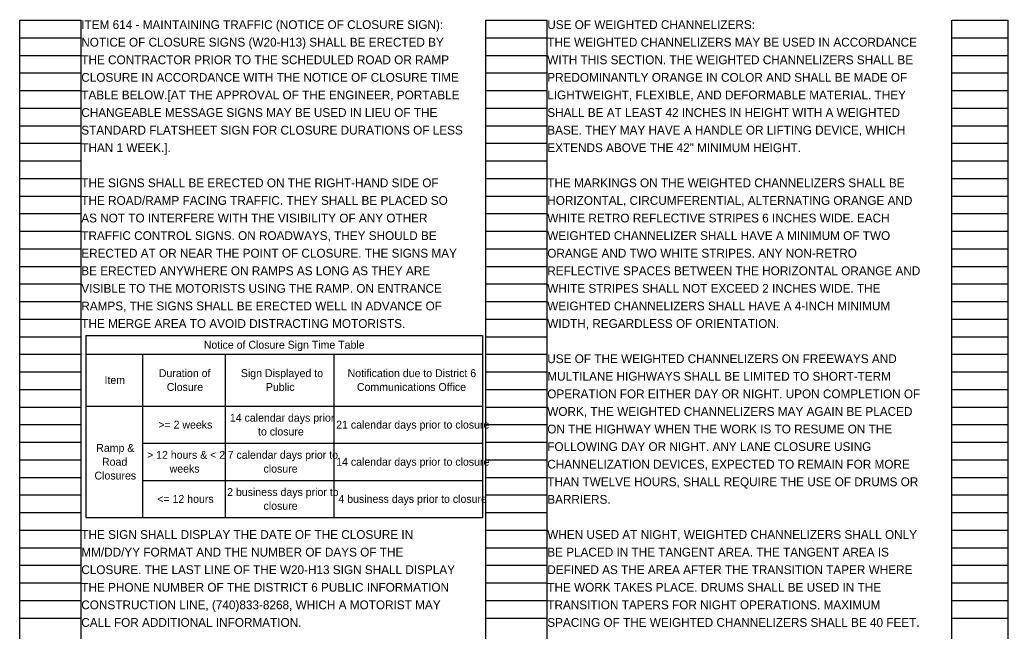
# Model space of a CAD drawing. Extents: x 63 to 145.9, y -75 to 21.1.
# Drawn here: x 79.23 to 94.97, y 11.41 to 21.15 of the extents above; entities that cross this region are included whole.
import ezdxf

# ---------------------------------------------------------------- set-up
doc = ezdxf.new("R2010")
doc.units = 0
doc.layers.add('AP_P_Airside', color=7, linetype='Continuous')
doc.layers.add('SC_Scratch1', color=7, linetype='Continuous')

msp = doc.modelspace()

# ---------------------------------------------------------------- linework, layer by layer
at = {"layer": 'AP_P_Airside'}
for p, q in [((80.277, 16.12), (86.593, 16.12)), ((80.277, 16.12), (80.277, 13.221)), ((86.593, 16.12), (86.593, 13.221)), ((80.277, 15.824), (86.593, 15.824)), ((81.179, 15.824), (81.179, 13.221)), ((82.496, 15.824), (82.496, 13.221)), ((84.226, 15.824), (84.226, 13.221)), ((80.277, 14.996), (86.593, 14.996)), ((81.179, 14.404), (86.593, 14.404)), ((81.179, 13.813), (86.593, 13.813)), ((80.277, 13.221), (86.593, 13.221))]:
    msp.add_line(p, q, dxfattribs=at)
at = {"layer": 'SC_Scratch1'}
for p, q in [((79.226, 0.98), (79.226, 21.14)), ((79.226, 21.14), (80.206, 21.14)), ((80.206, 0.98), (80.206, 21.14)), ((86.646, 0.98), (86.646, 21.14)), ((86.646, 21.14), (87.626, 21.14)), ((87.626, 0.98), (87.626, 21.14)), ((94.066, 0.98), (94.066, 21.14)), ((94.066, 21.14), (94.966, 21.14)), ((94.966, 0.98), (94.966, 21.14)), ((79.226, 20.86), (80.206, 20.86)), ((86.646, 20.86), (87.626, 20.86)), ((94.066, 20.86), (94.966, 20.86)), ((79.226, 20.58), (80.206, 20.58)), ((86.646, 20.58), (87.626, 20.58)), ((94.066, 20.58), (94.966, 20.58)), ((79.226, 20.3), (80.206, 20.3)), ((86.646, 20.3), (87.626, 20.3)), ((94.066, 20.3), (94.966, 20.3)), ((79.226, 20.02), (80.206, 20.02)), ((86.646, 20.02), (87.626, 20.02)), ((94.066, 20.02), (94.966, 20.02)), ((79.226, 19.74), (80.206, 19.74)), ((86.646, 19.74), (87.626, 19.74)), ((94.066, 19.74), (94.966, 19.74)), ((79.226, 19.46), (80.206, 19.46)), ((86.646, 19.46), (87.626, 19.46)), ((94.066, 19.46), (94.966, 19.46)), ((79.226, 19.18), (80.206, 19.18)), ((86.646, 19.18), (87.626, 19.18)), ((94.066, 19.18), (94.966, 19.18)), ((79.226, 18.9), (80.206, 18.9)), ((86.646, 18.9), (87.626, 18.9)), ((94.066, 18.9), (94.966, 18.9)), ((79.226, 18.62), (80.206, 18.62)), ((86.646, 18.62), (87.626, 18.62)), ((94.066, 18.62), (94.966, 18.62)), ((79.226, 18.34), (80.206, 18.34)), ((86.646, 18.34), (87.626, 18.34)), ((94.066, 18.34), (94.966, 18.34)), ((79.226, 18.06), (80.206, 18.06)), ((86.646, 18.06), (87.626, 18.06)), ((94.066, 18.06), (94.966, 18.06)), ((79.226, 17.78), (80.206, 17.78)), ((86.646, 17.78), (87.626, 17.78)), ((94.066, 17.78), (94.966, 17.78)), ((79.226, 17.5), (80.206, 17.5)), ((86.646, 17.5), (87.626, 17.5)), ((94.066, 17.5), (94.966, 17.5)), ((79.226, 17.22), (80.206, 17.22)), ((86.646, 17.22), (87.626, 17.22)), ((94.066, 17.22), (94.966, 17.22)), ((79.226, 16.94), (80.206, 16.94)), ((86.646, 16.94), (87.626, 16.94)), ((94.066, 16.94), (94.966, 16.94)), ((79.226, 16.66), (80.206, 16.66)), ((86.646, 16.66), (87.626, 16.66)), ((94.066, 16.66), (94.966, 16.66)), ((79.226, 16.38), (80.206, 16.38)), ((86.646, 16.38), (87.626, 16.38)), ((94.066, 16.38), (94.966, 16.38)), ((79.226, 16.1), (80.206, 16.1)), ((86.646, 16.1), (87.626, 16.1)), ((94.066, 16.1), (94.966, 16.1)), ((79.226, 15.82), (80.206, 15.82)), ((86.646, 15.82), (87.626, 15.82)), ((94.066, 15.82), (94.966, 15.82)), ((79.226, 15.54), (80.206, 15.54)), ((86.646, 15.54), (87.626, 15.54)), ((94.066, 15.54), (94.966, 15.54)), ((79.226, 15.26), (80.206, 15.26)), ((86.646, 15.26), (87.626, 15.26)), ((94.066, 15.26), (94.966, 15.26)), ((79.226, 14.98), (80.206, 14.98)), ((86.646, 14.98), (87.626, 14.98)), ((94.066, 14.98), (94.966, 14.98)), ((79.226, 14.7), (80.206, 14.7)), ((86.646, 14.7), (87.626, 14.7)), ((94.066, 14.7), (94.966, 14.7)), ((79.226, 14.42), (80.206, 14.42)), ((86.646, 14.42), (87.626, 14.42)), ((94.066, 14.42), (94.966, 14.42)), ((79.226, 14.14), (80.206, 14.14)), ((86.646, 14.14), (87.626, 14.14)), ((94.066, 14.14), (94.966, 14.14)), ((79.226, 13.86), (80.206, 13.86)), ((86.646, 13.86), (87.626, 13.86)), ((94.066, 13.86), (94.966, 13.86)), ((79.226, 13.58), (80.206, 13.58)), ((86.646, 13.58), (87.626, 13.58)), ((94.066, 13.58), (94.966, 13.58)), ((79.226, 13.3), (80.206, 13.3)), ((86.646, 13.3), (87.626, 13.3)), ((94.066, 13.3), (94.966, 13.3)), ((79.226, 13.02), (80.206, 13.02)), ((86.646, 13.02), (87.626, 13.02)), ((94.066, 13.02), (94.966, 13.02)), ((79.226, 12.74), (80.206, 12.74)), ((86.646, 12.74), (87.626, 12.74)), ((94.066, 12.74), (94.966, 12.74)), ((79.226, 12.46), (80.206, 12.46)), ((86.646, 12.46), (87.626, 12.46)), ((94.066, 12.46), (94.966, 12.46)), ((79.226, 12.18), (80.206, 12.18)), ((86.646, 12.18), (87.626, 12.18)), ((94.066, 12.18), (94.966, 12.18)), ((79.226, 11.9), (80.206, 11.9)), ((86.646, 11.9), (87.626, 11.9)), ((94.066, 11.9), (94.966, 11.9)), ((79.226, 11.62), (80.206, 11.62)), ((86.646, 11.62), (87.626, 11.62)), ((94.066, 11.62), (94.966, 11.62))]:
    msp.add_line(p, q, dxfattribs=at)

# ---------------------------------------------------------------- texts
at = {"layer": 'AP_P_Airside'}
for s, height, p in [('ITEM 614 - MAINTAINING TRAFFIC (NOTICE OF CLOSURE SIGN):', 0.14, (80.206, 21)), ('USE OF WEIGHTED CHANNELIZERS:', 0.14, (87.626, 21)), ('NOTICE OF CLOSURE SIGNS (W20-H13) SHALL BE ERECTED BY ', 0.14, (80.206, 20.72)), ('THE WEIGHTED CHANNELIZERS MAY BE USED IN ACCORDANCE ', 0.14, (87.626, 20.72)), ('THE CONTRACTOR PRIOR TO THE SCHEDULED ROAD OR RAMP ', 0.14, (80.206, 20.44)), ('WITH THIS SECTION. THE WEIGHTED CHANNELIZERS SHALL BE ', 0.14, (87.626, 20.44)), ('CLOSURE IN ACCORDANCE WITH THE NOTICE OF CLOSURE TIME ', 0.14, (80.206, 20.16)), ('PREDOMINANTLY ORANGE IN COLOR AND SHALL BE MADE OF ', 0.14, (87.626, 20.16)), ('TABLE BELOW.[AT THE APPROVAL OF THE ENGINEER, PORTABLE ', 0.14, (80.206, 19.88)), ('LIGHTWEIGHT, FLEXIBLE, AND DEFORMABLE MATERIAL. THEY ', 0.14, (87.626, 19.88)), ('CHANGEABLE MESSAGE SIGNS MAY BE USED IN LIEU OF THE ', 0.14, (80.206, 19.6)), ('SHALL BE AT LEAST 42 INCHES IN HEIGHT WITH A WEIGHTED ', 0.14, (87.626, 19.6)), ('STANDARD FLATSHEET SIGN FOR CLOSURE DURATIONS OF LESS ', 0.14, (80.206, 19.32)), ('BASE. THEY MAY HAVE A HANDLE OR LIFTING DEVICE, WHICH ', 0.14, (87.626, 19.32)), ('THAN 1 WEEK.].', 0.14, (80.206, 19.04)), ('EXTENDS ABOVE THE 42" MINIMUM HEIGHT.', 0.14, (87.626, 19.04)), ('THE SIGNS SHALL BE ERECTED ON THE RIGHT-HAND SIDE OF ', 0.14, (80.206, 18.48)), ('THE MARKINGS ON THE WEIGHTED CHANNELIZERS SHALL BE ', 0.14, (87.626, 18.48)), ('THE ROAD/RAMP FACING TRAFFIC. THEY SHALL BE PLACED SO ', 0.14, (80.206, 18.2)), ('HORIZONTAL, CIRCUMFERENTIAL, ALTERNATING ORANGE AND ', 0.14, (87.626, 18.2)), ('AS NOT TO INTERFERE WITH THE VISIBILITY OF ANY OTHER ', 0.14, (80.206, 17.92)), ('WHITE RETRO REFLECTIVE STRIPES 6 INCHES WIDE. EACH ', 0.14, (87.626, 17.92)), ('TRAFFIC CONTROL SIGNS. ON ROADWAYS, THEY SHOULD BE ', 0.14, (80.206, 17.64)), ('WEIGHTED CHANNELIZER SHALL HAVE A MINIMUM OF TWO ', 0.14, (87.626, 17.64)), ('ERECTED AT OR NEAR THE POINT OF CLOSURE. THE SIGNS MAY ', 0.14, (80.206, 17.36)), ('ORANGE AND TWO WHITE STRIPES. ANY NON-RETRO ', 0.14, (87.626, 17.36)), ('BE ERECTED ANYWHERE ON RAMPS AS LONG AS THEY ARE ', 0.14, (80.206, 17.08)), ('REFLECTIVE SPACES BETWEEN THE HORIZONTAL ORANGE AND ', 0.14, (87.626, 17.08)), ('VISIBLE TO THE MOTORISTS USING THE RAMP. ON ENTRANCE ', 0.14, (80.206, 16.8)), ('WHITE STRIPES SHALL NOT EXCEED 2 INCHES WIDE. THE ', 0.14, (87.626, 16.8)), ('RAMPS, THE SIGNS SHALL BE ERECTED WELL IN ADVANCE OF ', 0.14, (80.206, 16.52)), ('WEIGHTED CHANNELIZERS SHALL HAVE A 4-INCH MINIMUM ', 0.14, (87.626, 16.52)), ('THE MERGE AREA TO AVOID DISTRACTING MOTORISTS.', 0.14, (80.206, 16.24)), ('WIDTH, REGARDLESS OF ORIENTATION.', 0.14, (87.626, 16.24)), ('Notice of Closure Sign Time Table', 0.12573, (82.157, 15.909)), ('USE OF THE WEIGHTED CHANNELIZERS ON FREEWAYS AND ', 0.14, (87.626, 15.68)), ('Duration of ', 0.12573, (81.441, 15.457)), ('Sign Displayed to ', 0.12573, (82.747, 15.457)), ('Notification due to District 6 ', 0.12573, (84.447, 15.457)), ('Item', 0.1257, (80.576, 15.347)), ('MULTILANE HIGHWAYS SHALL BE LIMITED TO SHORT-TERM ', 0.14, (87.626, 15.4)), ('Closure', 0.1257, (81.567, 15.237)), ('Public', 0.1257, (83.145, 15.237)), ('Communications Office', 0.12573, (84.595, 15.237)), ('OPERATION FOR EITHER DAY OR NIGHT. UPON COMPLETION OF ', 0.14, (87.626, 15.12)), ('WORK, THE WEIGHTED CHANNELIZERS MAY AGAIN BE PLACED ', 0.14, (87.626, 14.84)), ('14 calendar days prior ', 0.12573, (82.572, 14.747)), ('>= 2 weeks', 0.1257, (81.433, 14.637)), ('to closure', 0.1257, (83.02, 14.527)), ('21 calendar days prior to closure', 0.12573, (84.265, 14.637)), ('ON THE HIGHWAY WHEN THE WORK IS TO RESUME ON THE ', 0.14, (87.626, 14.56)), ('Ramp & ', 0.1257, (80.444, 14.266)), ('FOLLOWING DAY OR NIGHT. ANY LANE CLOSURE USING ', 0.14, (87.626, 14.28)), ('Road ', 0.1257, (80.536, 14.046)), ('> 12 hours & < 2 ', 0.12573, (81.253, 14.156)), ('7 calendar days prior to ', 0.12573, (82.537, 14.156)), ('14 calendar days prior to closure', 0.12573, (84.265, 14.046)), ('weeks', 0.1257, (81.613, 13.936)), ('closure', 0.1257, (83.108, 13.936)), ('CHANNELIZATION DEVICES, EXPECTED TO REMAIN FOR MORE ', 0.14, (87.626, 14)), ('Closures', 0.1257, (80.416, 13.826)), ('THAN TWELVE HOURS, SHALL REQUIRE THE USE OF DRUMS OR ', 0.14, (87.626, 13.72)), ('2 business days prior to ', 0.12573, (82.528, 13.564)), ('<= 12 hours', 0.12573, (81.416, 13.454)), ('4 business days prior to closure', 0.12573, (84.3, 13.454)), ('BARRIERS.', 0.14, (87.626, 13.44)), ('closure', 0.1257, (83.108, 13.344)), ('THE SIGN SHALL DISPLAY THE DATE OF THE CLOSURE IN ', 0.14, (80.206, 12.88)), ('WHEN USED AT NIGHT, WEIGHTED CHANNELIZERS SHALL ONLY ', 0.14, (87.626, 12.88)), ('MM/DD/YY FORMAT AND THE NUMBER OF DAYS OF THE ', 0.14, (80.206, 12.6)), ('BE PLACED IN THE TANGENT AREA. THE TANGENT AREA IS ', 0.14, (87.626, 12.6)), ('CLOSURE. THE LAST LINE OF THE W20-H13 SIGN SHALL DISPLAY ', 0.14, (80.206, 12.32)), ('DEFINED AS THE AREA AFTER THE TRANSITION TAPER WHERE ', 0.14, (87.626, 12.32)), ('THE PHONE NUMBER OF THE DISTRICT 6 PUBLIC INFORMATION ', 0.14, (80.206, 12.04)), ('THE WORK TAKES PLACE. DRUMS SHALL BE USED IN THE ', 0.14, (87.626, 12.04)), ('CONSTRUCTION LINE, (740)833-8268, WHICH A MOTORIST MAY ', 0.14, (80.206, 11.76)), ('TRANSITION TAPERS FOR NIGHT OPERATIONS. MAXIMUM ', 0.14, (87.626, 11.76)), ('CALL FOR ADDITIONAL INFORMATION. ', 0.14, (80.206, 11.48)), ('SPACING OF THE WEIGHTED CHANNELIZERS SHALL BE 40 FEET. ', 0.14, (87.626, 11.48))]:
    msp.add_text(s, height=height, dxfattribs=at).set_placement(p)

doc.saveas('drawing.dxf')
